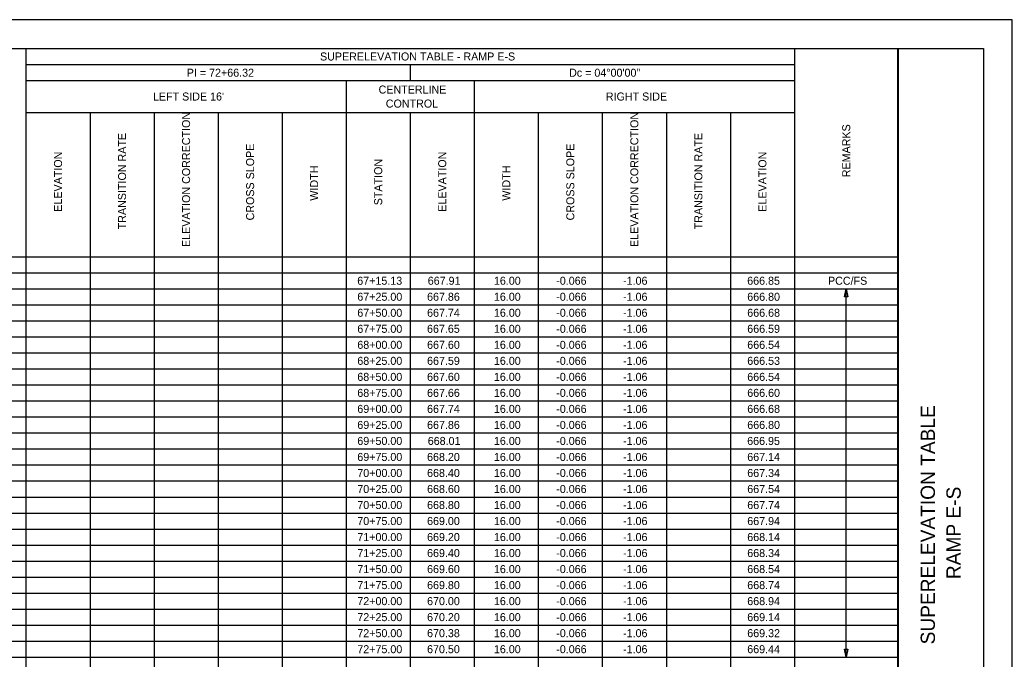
# Model space of a CAD drawing. Extents: x 0 to 34, y 0 to 22.
# Drawn here: x 16.64 to 34, y 10.83 to 22 of the extents above; entities that cross this region are included whole.
import ezdxf

# ---------------------------------------------------------------- set-up
doc = ezdxf.new("R2010")
doc.units = 0
for name, color, linetype in [('SH_Border', 7, 'Continuous'), ('SH_Cut_Line', 7, 'Continuous'), ('SH_Data', 7, 'Continuous'), ('SH_Text', 7, 'Continuous')]:
    doc.layers.add(name, color=color, linetype=linetype)

msp = doc.modelspace()

# ---------------------------------------------------------------- linework, layer by layer
at = {"layer": 'SH_Border'}
msp.add_line((32, 0.5), (32, 21.5), dxfattribs=at)
msp.add_lwpolyline([(1.5, 21.5), (33.5, 21.5), (33.5, 0.5), (1.5, 0.5)], close=True, dxfattribs=at)
at = {"layer": 'SH_Cut_Line'}
msp.add_lwpolyline([(0, 0), (34, 0), (34, 22), (0, 22)], close=True, dxfattribs=at)
at = {"layer": 'SH_Text'}
for p, q in [((1.5, 21.5), (16.752, 21.5)), ((16.752, 21.5), (16.752, 0.5)), ((16.752, 21.5), (32.004, 21.5)), ((16.752, 21.5), (16.752, 0.5)), ((30.192, 21.5), (30.192, 0.5)), ((32.004, 21.5), (32.004, 0.5)), ((16.752, 21.22), (30.192, 21.22)), ((23.472, 21.22), (23.472, 20.94)), ((16.752, 20.94), (30.192, 20.94)), ((22.352, 20.94), (22.352, 0.5)), ((24.592, 20.94), (24.592, 0.5)), ((16.752, 20.38), (30.192, 20.38)), ((17.872, 20.38), (17.872, 0.5)), ((18.992, 20.38), (18.992, 0.5)), ((20.112, 20.38), (20.112, 0.5)), ((21.232, 20.38), (21.232, 0.5)), ((23.472, 20.38), (23.472, 0.5)), ((25.712, 20.38), (25.712, 0.5)), ((26.832, 20.38), (26.832, 0.5)), ((27.952, 20.38), (27.952, 0.5)), ((29.072, 20.38), (29.072, 0.5)), ((1.5, 17.86), (16.752, 17.86)), ((16.752, 17.86), (32.004, 17.86)), ((1.5, 17.58), (16.752, 17.58)), ((16.752, 17.58), (32.004, 17.58)), ((1.5, 17.3), (16.752, 17.3)), ((16.752, 17.3), (32.004, 17.3)), ((31.098, 10.86), (31.098, 17.3)), ((1.5, 17.02), (16.752, 17.02)), ((16.752, 17.02), (32.004, 17.02)), ((1.5, 16.74), (16.752, 16.74)), ((16.752, 16.74), (32.004, 16.74)), ((1.5, 16.46), (16.752, 16.46)), ((16.752, 16.46), (32.004, 16.46)), ((1.5, 16.18), (16.752, 16.18)), ((16.752, 16.18), (32.004, 16.18)), ((1.5, 15.9), (16.752, 15.9)), ((16.752, 15.9), (32.004, 15.9)), ((1.5, 15.62), (16.752, 15.62)), ((16.752, 15.62), (32.004, 15.62)), ((1.5, 15.34), (16.752, 15.34)), ((16.752, 15.34), (32.004, 15.34)), ((1.5, 15.06), (16.752, 15.06)), ((16.752, 15.06), (32.004, 15.06)), ((1.5, 14.78), (16.752, 14.78)), ((16.752, 14.78), (32.004, 14.78)), ((1.5, 14.5), (16.752, 14.5)), ((16.752, 14.5), (32.004, 14.5)), ((1.5, 14.22), (16.752, 14.22)), ((16.752, 14.22), (32.004, 14.22)), ((1.5, 13.94), (16.752, 13.94)), ((16.752, 13.94), (32.004, 13.94)), ((1.5, 13.66), (16.752, 13.66)), ((16.752, 13.66), (32.004, 13.66)), ((1.5, 13.38), (16.752, 13.38)), ((16.752, 13.38), (32.004, 13.38)), ((1.5, 13.1), (16.752, 13.1)), ((16.752, 13.1), (32.004, 13.1)), ((1.5, 12.82), (16.752, 12.82)), ((16.752, 12.82), (32.004, 12.82)), ((1.5, 12.54), (16.752, 12.54)), ((16.752, 12.54), (32.004, 12.54)), ((1.5, 12.26), (16.752, 12.26)), ((16.752, 12.26), (32.004, 12.26)), ((1.5, 11.98), (16.752, 11.98)), ((16.752, 11.98), (32.004, 11.98)), ((1.5, 11.7), (16.752, 11.7)), ((16.752, 11.7), (32.004, 11.7)), ((1.5, 11.42), (16.752, 11.42)), ((16.752, 11.42), (32.004, 11.42)), ((1.5, 11.14), (16.752, 11.14)), ((16.752, 11.14), (32.004, 11.14)), ((1.5, 10.86), (16.752, 10.86)), ((16.752, 10.86), (32.004, 10.86))]:
    msp.add_line(p, q, dxfattribs=at)
for points in [[(31.07, 17.16), (31.098, 17.3), (31.126, 17.16)], [(31.126, 11), (31.098, 10.86), (31.07, 11)]]:
    msp.add_lwpolyline(points, close=True, dxfattribs=at)

# ---------------------------------------------------------------- texts
at = {"layer": 'SH_Data'}
for s, p in [('SUPERELEVATION TABLE', (32.65, 11.084)), ('RAMP E-S', (33.1, 12.225))]:
    msp.add_text(s, height=0.25, rotation=90, dxfattribs=at).set_placement(p)
at = {"layer": 'SH_Text'}
for s, p in [('SUPERELEVATION TABLE - RAMP E-S', (21.895, 21.29)), ('PI = 72+66.32', (19.564, 21.006)), ('Dc = 04°00\'00"', (26.251, 21.006)), ('CENTERLINE', (22.919, 20.712)), ("LEFT SIDE 16'", (18.973, 20.59)), ('RIGHT SIDE', (26.894, 20.59)), ('CONTROL', (23.045, 20.467)), ('67+15.13', (22.546, 17.37)), ('667.91', (23.779, 17.37)), ('16.00', (24.936, 17.37)), ('-0.066', (26.026, 17.37)), ('-1.06', (27.195, 17.37)), ('666.85', (29.366, 17.37)), ('PCC/FS', (30.779, 17.37)), ('67+25.00', (22.547, 17.09)), ('667.86', (23.767, 17.09)), ('16.00', (24.936, 17.09)), ('-0.066', (26.026, 17.09)), ('-1.06', (27.195, 17.09)), ('666.80', (29.367, 17.09)), ('67+50.00', (22.547, 16.81)), ('667.74', (23.767, 16.81)), ('16.00', (24.936, 16.81)), ('-0.066', (26.026, 16.81)), ('-1.06', (27.195, 16.81)), ('666.68', (29.367, 16.81)), ('67+75.00', (22.547, 16.53)), ('667.65', (23.766, 16.53)), ('16.00', (24.936, 16.53)), ('-0.066', (26.026, 16.53)), ('-1.06', (27.195, 16.53)), ('666.59', (29.367, 16.53)), ('68+00.00', (22.547, 16.25)), ('667.60', (23.767, 16.25)), ('16.00', (24.936, 16.25)), ('-0.066', (26.026, 16.25)), ('-1.06', (27.195, 16.25)), ('666.54', (29.367, 16.25)), ('68+25.00', (22.547, 15.97)), ('667.59', (23.767, 15.97)), ('16.00', (24.936, 15.97)), ('-0.066', (26.026, 15.97)), ('-1.06', (27.195, 15.97)), ('666.53', (29.367, 15.97)), ('68+50.00', (22.547, 15.69)), ('667.60', (23.767, 15.69)), ('16.00', (24.936, 15.69)), ('-0.066', (26.026, 15.69)), ('-1.06', (27.195, 15.69)), ('666.54', (29.367, 15.69)), ('68+75.00', (22.547, 15.41)), ('667.66', (23.767, 15.41)), ('16.00', (24.936, 15.41)), ('-0.066', (26.026, 15.41)), ('-1.06', (27.195, 15.41)), ('666.60', (29.367, 15.41)), ('69+00.00', (22.547, 15.13)), ('667.74', (23.767, 15.13)), ('16.00', (24.936, 15.13)), ('-0.066', (26.026, 15.13)), ('-1.06', (27.195, 15.13)), ('666.68', (29.367, 15.13)), ('69+25.00', (22.547, 14.85)), ('667.86', (23.767, 14.85)), ('16.00', (24.936, 14.85)), ('-0.066', (26.026, 14.85)), ('-1.06', (27.195, 14.85)), ('666.80', (29.367, 14.85)), ('69+50.00', (22.547, 14.57)), ('668.01', (23.779, 14.57)), ('16.00', (24.936, 14.57)), ('-0.066', (26.026, 14.57)), ('-1.06', (27.195, 14.57)), ('666.95', (29.366, 14.57)), ('69+75.00', (22.547, 14.29)), ('668.20', (23.767, 14.29)), ('16.00', (24.936, 14.29)), ('-0.066', (26.026, 14.29)), ('-1.06', (27.195, 14.29)), ('667.14', (29.367, 14.29)), ('70+00.00', (22.547, 14.01)), ('668.40', (23.767, 14.01)), ('16.00', (24.936, 14.01)), ('-0.066', (26.026, 14.01)), ('-1.06', (27.195, 14.01)), ('667.34', (29.367, 14.01)), ('70+25.00', (22.547, 13.73)), ('668.60', (23.767, 13.73)), ('16.00', (24.936, 13.73)), ('-0.066', (26.026, 13.73)), ('-1.06', (27.195, 13.73)), ('667.54', (29.367, 13.73)), ('70+50.00', (22.547, 13.45)), ('668.80', (23.767, 13.45)), ('16.00', (24.936, 13.45)), ('-0.066', (26.026, 13.45)), ('-1.06', (27.195, 13.45)), ('667.74', (29.367, 13.45)), ('70+75.00', (22.547, 13.17)), ('669.00', (23.767, 13.17)), ('16.00', (24.936, 13.17)), ('-0.066', (26.026, 13.17)), ('-1.06', (27.195, 13.17)), ('667.94', (29.367, 13.17)), ('71+00.00', (22.547, 12.89)), ('669.20', (23.767, 12.89)), ('16.00', (24.936, 12.89)), ('-0.066', (26.026, 12.89)), ('-1.06', (27.195, 12.89)), ('668.14', (29.367, 12.89)), ('71+25.00', (22.547, 12.61)), ('669.40', (23.767, 12.61)), ('16.00', (24.936, 12.61)), ('-0.066', (26.026, 12.61)), ('-1.06', (27.195, 12.61)), ('668.34', (29.367, 12.61)), ('71+50.00', (22.547, 12.33)), ('669.60', (23.767, 12.33)), ('16.00', (24.936, 12.33)), ('-0.066', (26.026, 12.33)), ('-1.06', (27.195, 12.33)), ('668.54', (29.367, 12.33)), ('71+75.00', (22.547, 12.05)), ('669.80', (23.767, 12.05)), ('16.00', (24.936, 12.05)), ('-0.066', (26.026, 12.05)), ('-1.06', (27.195, 12.05)), ('668.74', (29.367, 12.05)), ('72+00.00', (22.547, 11.77)), ('670.00', (23.767, 11.77)), ('16.00', (24.936, 11.77)), ('-0.066', (26.026, 11.77)), ('-1.06', (27.195, 11.77)), ('668.94', (29.367, 11.77)), ('72+25.00', (22.547, 11.49)), ('670.20', (23.767, 11.49)), ('16.00', (24.936, 11.49)), ('-0.066', (26.026, 11.49)), ('-1.06', (27.195, 11.49)), ('669.14', (29.367, 11.49)), ('72+50.00', (22.547, 11.21)), ('670.38', (23.767, 11.21)), ('16.00', (24.936, 11.21)), ('-0.066', (26.026, 11.21)), ('-1.06', (27.195, 11.21)), ('669.32', (29.367, 11.21)), ('72+75.00', (22.547, 10.93)), ('670.50', (23.767, 10.93)), ('16.00', (24.936, 10.93)), ('-0.066', (26.026, 10.93)), ('-1.06', (27.195, 10.93)), ('669.44', (29.367, 10.93))]:
    msp.add_text(s, height=0.14, dxfattribs=at).set_placement(p)
for s, p in [('ELEVATION CORRECTION', (19.622, 18.03)), ('ELEVATION CORRECTION', (27.462, 18.03)), ('REMARKS', (31.168, 19.249)), ('TRANSITION RATE', (18.502, 18.339)), ('TRANSITION RATE', (28.582, 18.339)), ('CROSS SLOPE', (20.742, 18.494)), ('CROSS SLOPE', (26.342, 18.494)), ('ELEVATION', (17.382, 18.646)), ('ELEVATION', (24.102, 18.646)), ('ELEVATION', (29.702, 18.646)), ('STATION', (22.982, 18.759)), ('WIDTH', (21.862, 18.839)), ('WIDTH', (25.222, 18.839))]:
    msp.add_text(s, height=0.14, rotation=90, dxfattribs=at).set_placement(p)

doc.saveas('drawing.dxf')
